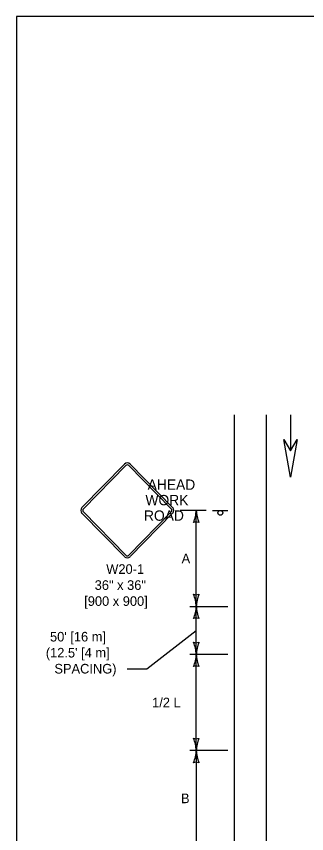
# Model space of a CAD drawing. Extents: x 49991.4 to 50021, y 49987.6 to 50011.4.
# Drawn here: x 50000.34 to 50002.15, y 50006.16 to 50011.26 of the extents above; entities that cross this region are included whole.
import ezdxf

# ---------------------------------------------------------------- set-up
doc = ezdxf.new("R2010")
doc.units = 0
for name, color, linetype in [('Level 1', 7, 'Continuous'), ('Level 2', 7, 'Continuous'), ('Level 3', 7, 'Continuous')]:
    doc.layers.add(name, color=color, linetype=linetype)

msp = doc.modelspace()

# ---------------------------------------------------------------- linework, layer by layer
at = {"layer": 'Level 1'}
for p, q in [((50001.6979, 50000.4631), (50001.6979, 50008.7736)), ((50001.8979, 50000.4631), (50001.8979, 50008.7736)), ((50002.0477, 50008.7736), (50002.0477, 50008.5477)), ((50002.0479, 50008.7736), (50002.0479, 50008.5477)), ((50000.7456, 50008.194), (50001.0108, 50008.4647)), ((50000.7545, 50008.1854), (50001.0197, 50008.456)), ((50001.0383, 50008.456), (50001.3035, 50008.1854)), ((50001.0471, 50008.4647), (50001.3123, 50008.194)), ((50001.0197, 50007.8958), (50000.7545, 50008.1665)), ((50001.3035, 50008.1665), (50001.0383, 50007.8958)), ((50001.5619, 50008.176), (50001.6579, 50008.176)), ((50001.0108, 50007.8871), (50000.7456, 50008.1578)), ((50001.3123, 50008.1578), (50001.0471, 50007.8871))]:
    msp.add_line(p, q, dxfattribs=at)
for points in [[(50008.6146, 50011.2628), (50000.3356, 50011.2628), (50000.3356, 50000.0624), (50008.6146, 50000.0624)], [(50002.0897, 50008.62), (50002.0479, 50008.3835), (50002.0061, 50008.62), (50002.0479, 50008.5478)]]:
    msp.add_lwpolyline(points, close=True, dxfattribs=at)
msp.add_circle((50001.6099, 50008.1608), 0.0152, dxfattribs=at)
for centre, major_axis, ratio, start_param, end_param in [((50001.029, 50008.4466), (0, 0.0258), 0.98963, 5.497795, 7.068583), ((50001.029, 50008.4466), (0, 0.0134), 0.98, 5.497795, 7.068583), ((50000.7637, 50008.176), (0, -0.0258), 0.98963, 3.926991, 5.497787), ((50000.7637, 50008.176), (0, -0.0134), 0.98, 3.926991, 5.497787), ((50001.2941, 50008.176), (0.0134, 0), 0.98, 5.497787, 7.068583), ((50001.2941, 50008.176), (0.0258, 0), 0.98963, 5.497787, 7.068583), ((50001.029, 50007.9053), (0, -0.0258), 0.98963, 5.497787, 7.068583), ((50001.029, 50007.9053), (0, -0.0134), 0.98, 5.497787, 7.068583)]:
    msp.add_ellipse(centre, major_axis=major_axis, ratio=ratio, start_param=start_param, end_param=end_param, dxfattribs=at)
at = {"layer": 'Level 3'}
for p, q in [((50001.5219, 50008.176), (50001.3599, 50008.176)), ((50001.4599, 50007.576), (50001.4599, 50008.176)), ((50001.4199, 50007.576), (50001.6579, 50007.576)), ((50001.4599, 50007.276), (50001.4599, 50007.576)), ((50001.1516, 50007.1871), (50001.4599, 50007.426)), ((50001.6579, 50007.276), (50001.4199, 50007.276)), ((50001.4599, 50006.676), (50001.4599, 50007.276)), ((50001.0283, 50007.1871), (50001.1516, 50007.1871)), ((50001.6579, 50006.676), (50001.4199, 50006.676)), ((50001.4599, 50006.676), (50001.4599, 50006.076))]:
    msp.add_line(p, q, dxfattribs=at)
for centre, radius, start, end in [((50001.2271, 50008.1875), 0.233, 337.9228, 357.1727), ((50001.682, 50008.1852), 0.2223, 182.3605, 202.544), ((50001.4599, 50008.0478), 0.0548, 72.1388, 107.8612), ((50001.4599, 50007.7042), 0.0548, 252.1388, 287.8612), ((50001.2271, 50007.5645), 0.233, 2.8273, 22.0772), ((50001.682, 50007.5668), 0.2223, 157.456, 177.6395), ((50001.2377, 50007.5852), 0.2223, 337.456, 357.6395), ((50001.6926, 50007.5875), 0.233, 182.8273, 202.0772), ((50001.4599, 50007.4478), 0.0548, 72.1388, 107.8612), ((50001.4599, 50007.4042), 0.0548, 252.1388, 287.8612), ((50001.2271, 50007.2645), 0.233, 2.8273, 22.0772), ((50001.682, 50007.2668), 0.2223, 157.456, 177.6395), ((50001.2377, 50007.2852), 0.2223, 337.456, 357.6395), ((50001.6926, 50007.2875), 0.233, 182.8273, 202.0772), ((50001.4599, 50007.1478), 0.0548, 72.1388, 107.8612), ((50001.4599, 50006.8042), 0.0548, 252.1388, 287.8612), ((50001.2271, 50006.6645), 0.233, 2.8273, 22.0772), ((50001.682, 50006.6668), 0.2223, 157.456, 177.6395), ((50001.2377, 50006.6852), 0.2223, 337.456, 357.6395), ((50001.6926, 50006.6875), 0.233, 182.8273, 202.0772), ((50001.4599, 50006.5478), 0.0548, 72.1388, 107.8612)]:
    msp.add_arc(centre, radius, start, end, dxfattribs=at)

# ---------------------------------------------------------------- texts
at = {"layer": 'Level 1'}
for s, p in [('AHEAD', (50001.156, 50008.3049)), ('WORK', (50001.1422, 50008.2082)), ('ROAD', (50001.1332, 50008.1114))]:
    msp.add_text(s, height=0.06453, rotation=360, dxfattribs=at).set_placement(p)
at = {"layer": 'Level 2'}
msp.add_text('A', height=0.06, rotation=0, dxfattribs=at).set_placement((50001.3683, 50007.846))
for s, p in [('W20-1', (50000.8974, 50007.7796)), ('36" x 36"', (50000.8251, 50007.6796)), ('[900 x 900]', (50000.7596, 50007.5796)), ("50' [16 m]", (50000.546, 50007.3571)), ("(12.5' [4 m]", (50000.5198, 50007.2571)), ('SPACING)', (50000.5734, 50007.1571)), ('1/2 L', (50001.184, 50006.946)), ('B', (50001.3643, 50006.347))]:
    msp.add_text(s, height=0.06, dxfattribs=at).set_placement(p)

doc.saveas('drawing.dxf')
